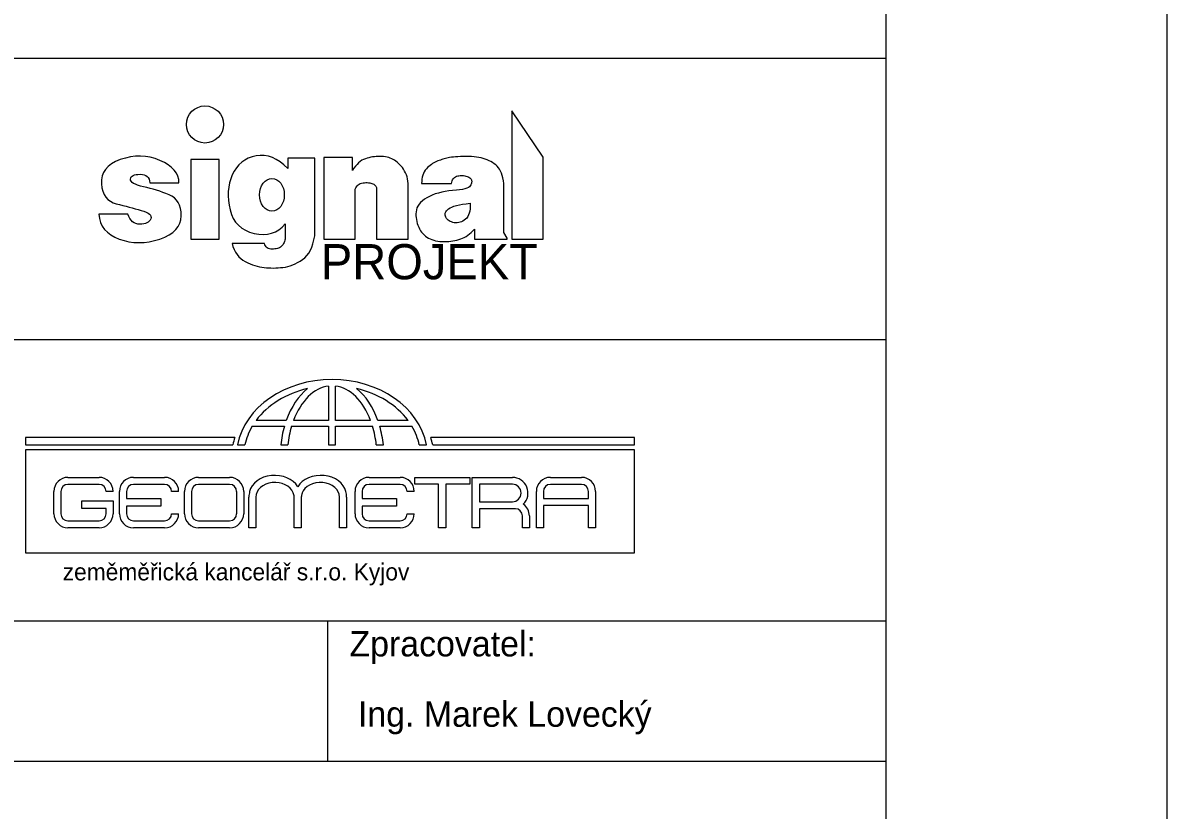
# Model space of a CAD drawing. Extents: x 1983 to 3683, y -706 to -261.
# Drawn here: x 2856.3 to 2937.6, y -606.5 to -550.5 of the extents above; entities that cross this region are included whole.
import ezdxf

# ---------------------------------------------------------------- set-up
doc = ezdxf.new("R2010")
doc.units = 0
for name, color, linetype in [('Default', 7, 'Continuous'), ('Komunikace', 7, 'Continuous'), ('Křížky', 7, 'Continuous'), ('Svazek obcí-chráničky', 7, 'Continuous'), ('Vrstva 51', 7, 'Continuous')]:
    doc.layers.add(name, color=color, linetype=linetype)

msp = doc.modelspace()

# ---------------------------------------------------------------- linework, layer by layer
at = {"layer": 'Default'}
msp.add_lwpolyline([(2727.602, -705.008), (2937.602, -705.008), (2937.602, -408.008), (2727.602, -408.008)], close=True, dxfattribs=at)
at = {"layer": 'Komunikace'}
for points in [[(2893.266, -565.887), (2893.266, -560.047), (2891.026, -556.767), (2891.026, -565.887), (2893.266, -565.887)], [(2864.538, -566.122), (2864.9, -566.105), (2865.266, -566.058), (2865.637, -565.979), (2866.013, -565.868), (2866.368, -565.732), (2866.676, -565.576), (2866.937, -565.4), (2867.151, -565.204), (2867.318, -564.988), (2867.439, -564.752), (2867.512, -564.496), (2867.539, -564.22), (2867.528, -563.947), (2867.49, -563.698), (2867.424, -563.474), (2867.33, -563.274), (2867.209, -563.1), (2867.059, -562.95), (2866.882, -562.824), (2866.678, -562.723), (2866.458, -562.637), (2866.236, -562.556), (2866.012, -562.478), (2865.786, -562.405), (2865.557, -562.337), (2865.326, -562.273), (2865.092, -562.213), (2864.857, -562.158), (2864.635, -562.103), (2864.444, -562.043), (2864.283, -561.98), (2864.153, -561.913), (2864.053, -561.842), (2863.983, -561.767), (2863.944, -561.688), (2863.936, -561.605), (2863.952, -561.525), (2863.989, -561.456), (2864.045, -561.398), (2864.121, -561.351), (2864.217, -561.315), (2864.332, -561.289), (2864.468, -561.275), (2864.623, -561.271), (2864.778, -561.282), (2864.914, -561.311), (2865.029, -561.358), (2865.123, -561.424), (2865.198, -561.508), (2865.253, -561.61), (2865.287, -561.73), (2865.302, -561.869), (2867.381, -561.869), (2867.361, -561.628), (2867.299, -561.398), (2867.194, -561.181), (2867.046, -560.976), (2866.856, -560.785), (2866.622, -560.606), (2866.345, -560.44), (2866.026, -560.287), (2865.684, -560.157), (2865.339, -560.063), (2864.991, -560.003), (2864.641, -559.978), (2864.288, -559.988), (2863.932, -560.033), (2863.574, -560.113), (2863.213, -560.227), (2862.875, -560.369), (2862.586, -560.532), (2862.345, -560.716), (2862.153, -560.919), (2862.009, -561.144), (2861.915, -561.389), (2861.868, -561.654), (2861.871, -561.94), (2861.91, -562.221), (2861.976, -562.473), (2862.069, -562.696), (2862.187, -562.889), (2862.332, -563.052), (2862.503, -563.186), (2862.7, -563.29), (2862.923, -563.365), (2863.158, -563.425), (2863.389, -563.484), (2863.617, -563.544), (2863.841, -563.603), (2864.061, -563.661), (2864.278, -563.72), (2864.491, -563.778), (2864.701, -563.835), (2864.893, -563.895), (2865.054, -563.96), (2865.185, -564.029), (2865.284, -564.102), (2865.353, -564.18), (2865.391, -564.262), (2865.398, -564.349), (2865.374, -564.441), (2865.327, -564.529), (2865.266, -564.605), (2865.191, -564.67), (2865.101, -564.723), (2864.997, -564.764), (2864.878, -564.794), (2864.745, -564.812), (2864.598, -564.819), (2864.45, -564.809), (2864.314, -564.776), (2864.19, -564.72), (2864.079, -564.641), (2863.98, -564.54), (2863.894, -564.416), (2863.82, -564.27), (2863.758, -564.102), (2861.678, -564.102), (2861.722, -564.408), (2861.805, -564.69), (2861.928, -564.948), (2862.091, -565.182), (2862.293, -565.391), (2862.535, -565.577), (2862.816, -565.737), (2863.137, -565.874), (2863.48, -565.983), (2863.828, -566.061), (2864.181, -566.107), (2864.538, -566.122)], [(2870.226, -565.887), (2870.226, -560.207), (2868.226, -560.207), (2868.226, -565.887), (2870.226, -565.887)], [(2874.086, -567.929), (2874.254, -567.926), (2874.424, -567.917), (2874.596, -567.904), (2874.77, -567.885), (2874.944, -567.858), (2875.118, -567.819), (2875.292, -567.768), (2875.465, -567.705), (2875.638, -567.629), (2875.811, -567.542), (2875.984, -567.442), (2876.156, -567.33), (2876.32, -567.2), (2876.469, -567.048), (2876.601, -566.872), (2876.718, -566.673), (2876.819, -566.451), (2876.904, -566.206), (2876.973, -565.938), (2877.026, -565.647), (2877.026, -560.127), (2875.106, -560.127), (2875.106, -560.847), (2874.84, -560.593), (2874.57, -560.379), (2874.295, -560.207), (2874.016, -560.076), (2873.733, -559.986), (2873.446, -559.938), (2873.154, -559.93), (2872.858, -559.963), (2872.571, -560.032), (2872.306, -560.128), (2872.062, -560.254), (2871.84, -560.408), (2871.64, -560.59), (2871.462, -560.801), (2871.306, -561.04), (2871.171, -561.308), (2871.06, -561.594), (2870.975, -561.887), (2870.916, -562.187), (2870.883, -562.495), (2870.876, -562.809), (2870.895, -563.131), (2870.94, -563.46), (2871.011, -563.796), (2871.111, -564.119), (2871.243, -564.41), (2871.409, -564.668), (2871.607, -564.893), (2871.838, -565.086), (2872.101, -565.246), (2872.397, -565.373), (2872.726, -565.468), (2873.062, -565.526), (2873.381, -565.544), (2873.681, -565.52), (2873.964, -565.456), (2874.229, -565.351), (2874.477, -565.206), (2874.707, -565.02), (2874.918, -564.793), (2874.918, -565.87), (2874.9, -565.957), (2874.877, -566.039), (2874.849, -566.115), (2874.817, -566.185), (2874.781, -566.249), (2874.74, -566.308), (2874.694, -566.361), (2874.644, -566.408), (2874.588, -566.45), (2874.526, -566.486), (2874.456, -566.517), (2874.379, -566.543), (2874.295, -566.563), (2874.204, -566.578), (2874.106, -566.587), (2874.001, -566.591), (2873.897, -566.586), (2873.804, -566.567), (2873.72, -566.535), (2873.647, -566.49), (2873.584, -566.432), (2873.532, -566.36), (2873.489, -566.275), (2873.457, -566.177), (2871.15, -566.177), (2871.219, -566.405), (2871.302, -566.614), (2871.399, -566.804), (2871.51, -566.975), (2871.635, -567.128), (2871.773, -567.262), (2871.926, -567.377), (2872.092, -567.474), (2872.264, -567.556), (2872.435, -567.63), (2872.604, -567.696), (2872.772, -567.753), (2872.938, -567.801), (2873.103, -567.841), (2873.266, -567.872), (2873.428, -567.895), (2873.59, -567.911), (2873.753, -567.922), (2873.919, -567.928), (2874.086, -567.929)], [(2883.666, -565.887), (2883.666, -562.087), (2883.663, -561.917), (2883.649, -561.754), (2883.624, -561.597), (2883.589, -561.447), (2883.543, -561.304), (2883.486, -561.167), (2883.418, -561.036), (2883.339, -560.913), (2883.254, -560.796), (2883.167, -560.688), (2883.078, -560.589), (2882.987, -560.497), (2882.894, -560.413), (2882.799, -560.338), (2882.702, -560.271), (2882.603, -560.212), (2882.501, -560.161), (2882.395, -560.117), (2882.284, -560.079), (2882.169, -560.049), (2882.049, -560.025), (2881.926, -560.009), (2881.798, -559.999), (2881.666, -559.996), (2881.532, -559.999), (2881.399, -560.008), (2881.268, -560.021), (2881.138, -560.039), (2881.009, -560.062), (2880.881, -560.089), (2880.754, -560.122), (2880.629, -560.16), (2880.505, -560.208), (2880.384, -560.273), (2880.265, -560.354), (2880.149, -560.452), (2880.034, -560.566), (2879.923, -560.696), (2879.813, -560.844), (2879.706, -561.007), (2879.706, -560.087), (2877.666, -560.087), (2877.666, -565.887), (2879.906, -565.887), (2879.906, -562.327), (2879.941, -562.236), (2879.985, -562.155), (2880.039, -562.084), (2880.104, -562.023), (2880.178, -561.972), (2880.262, -561.931), (2880.356, -561.9), (2880.46, -561.879), (2880.566, -561.866), (2880.666, -561.859), (2880.762, -561.858), (2880.852, -561.864), (2880.937, -561.875), (2881.017, -561.893), (2881.091, -561.916), (2881.16, -561.946), (2881.223, -561.981), (2881.277, -562.019), (2881.322, -562.061), (2881.36, -562.107), (2881.389, -562.156), (2881.41, -562.21), (2881.422, -562.266), (2881.426, -562.327), (2881.426, -565.887), (2883.666, -565.887)], [(2886.229, -566.051), (2886.391, -566.048), (2886.548, -566.04), (2886.702, -566.025), (2886.851, -566.005), (2886.995, -565.979), (2887.135, -565.948), (2887.271, -565.91), (2887.403, -565.867), (2887.532, -565.816), (2887.659, -565.755), (2887.784, -565.683), (2887.908, -565.6), (2888.03, -565.508), (2888.15, -565.404), (2888.269, -565.291), (2888.386, -565.167), (2888.386, -565.887), (2890.706, -565.887), (2890.706, -565.807), (2890.466, -565.407), (2890.466, -561.927), (2890.44, -561.722), (2890.404, -561.532), (2890.359, -561.357), (2890.304, -561.195), (2890.239, -561.049), (2890.165, -560.916), (2890.082, -560.798), (2889.989, -560.695), (2889.888, -560.602), (2889.78, -560.517), (2889.667, -560.438), (2889.547, -560.366), (2889.421, -560.301), (2889.288, -560.243), (2889.15, -560.192), (2889.005, -560.147), (2888.853, -560.11), (2888.694, -560.077), (2888.527, -560.051), (2888.354, -560.03), (2888.173, -560.015), (2887.985, -560.006), (2887.79, -560.002), (2887.588, -560.004), (2887.389, -560.01), (2887.205, -560.019), (2887.036, -560.029), (2886.881, -560.042), (2886.741, -560.057), (2886.616, -560.074), (2886.506, -560.093), (2886.41, -560.115), (2886.322, -560.139), (2886.232, -560.165), (2886.142, -560.192), (2886.051, -560.222), (2885.96, -560.253), (2885.868, -560.287), (2885.775, -560.322), (2885.682, -560.359), (2885.589, -560.401), (2885.496, -560.45), (2885.405, -560.505), (2885.315, -560.567), (2885.226, -560.636), (2885.138, -560.712), (2885.05, -560.795), (2884.964, -560.884), (2884.884, -560.982), (2884.815, -561.089), (2884.756, -561.205), (2884.709, -561.331), (2884.672, -561.466), (2884.646, -561.61), (2884.631, -561.764), (2884.626, -561.927), (2886.746, -561.927), (2886.762, -561.831), (2886.786, -561.743), (2886.819, -561.665), (2886.86, -561.597), (2886.91, -561.537), (2886.969, -561.486), (2887.036, -561.445), (2887.112, -561.413), (2887.193, -561.388), (2887.274, -561.37), (2887.355, -561.359), (2887.437, -561.354), (2887.52, -561.356), (2887.603, -561.364), (2887.687, -561.379), (2887.771, -561.4), (2887.851, -561.426), (2887.923, -561.454), (2887.985, -561.484), (2888.039, -561.516), (2888.084, -561.55), (2888.121, -561.586), (2888.148, -561.625), (2888.167, -561.665), (2888.178, -561.708), (2888.183, -561.754), (2888.182, -561.803), (2888.175, -561.854), (2888.161, -561.908), (2888.141, -561.965), (2888.115, -562.025), (2888.082, -562.087), (2888.032, -562.149), (2887.951, -562.205), (2887.839, -562.255), (2887.698, -562.301), (2887.526, -562.341), (2887.323, -562.375), (2887.091, -562.405), (2886.828, -562.429), (2886.556, -562.456), (2886.296, -562.493), (2886.049, -562.541), (2885.814, -562.599), (2885.591, -562.668), (2885.381, -562.748), (2885.183, -562.838), (2884.997, -562.939), (2884.828, -563.047), (2884.679, -563.159), (2884.552, -563.277), (2884.445, -563.398), (2884.36, -563.524), (2884.295, -563.655), (2884.251, -563.79), (2884.228, -563.93), (2884.22, -564.071), (2884.221, -564.212), (2884.231, -564.351), (2884.25, -564.489), (2884.278, -564.625), (2884.315, -564.761), (2884.361, -564.895), (2884.416, -565.028), (2884.479, -565.156), (2884.549, -565.276), (2884.626, -565.386), (2884.709, -565.487), (2884.8, -565.58), (2884.898, -565.664), (2885.002, -565.739), (2885.114, -565.805), (2885.232, -565.862), (2885.356, -565.913), (2885.486, -565.955), (2885.622, -565.989), (2885.765, -566.016), (2885.913, -566.036), (2886.068, -566.047), (2886.229, -566.051)], [(2886.945, -564.707), (2886.842, -564.686), (2886.747, -564.658), (2886.66, -564.622), (2886.581, -564.578), (2886.511, -564.527), (2886.448, -564.468), (2886.393, -564.401), (2886.346, -564.327), (2886.312, -564.249), (2886.294, -564.172), (2886.293, -564.096), (2886.308, -564.021), (2886.341, -563.947), (2886.39, -563.873), (2886.456, -563.801), (2886.538, -563.73), (2886.642, -563.661), (2886.77, -563.598), (2886.924, -563.541), (2887.103, -563.488), (2887.307, -563.441), (2887.537, -563.399), (2887.791, -563.363), (2888.071, -563.331), (2888.075, -563.53), (2888.067, -563.712), (2888.045, -563.878), (2888.01, -564.028), (2887.963, -564.161), (2887.902, -564.279), (2887.829, -564.38), (2887.743, -564.465), (2887.649, -564.536), (2887.554, -564.596), (2887.457, -564.644), (2887.358, -564.68), (2887.257, -564.704), (2887.155, -564.717), (2887.051, -564.717), (2886.945, -564.707)]]:
    msp.add_lwpolyline(points, dxfattribs=at)
msp.add_circle((2869.226, -557.727), 1.32, dxfattribs=at)
msp.add_ellipse((2873.986, -562.727), major_axis=(0, 1.16), ratio=0.758621, dxfattribs=at)
at = {"layer": 'Křížky'}
msp.add_lwpolyline([(2747.602, -428.008), (2917.602, -428.008), (2917.602, -688.008), (2747.602, -688.008)], close=True, dxfattribs=at)
at = {"layer": 'Svazek obcí-chráničky'}
for p, q in [((2877.997, -576.321), (2877.997, -578.766)), ((2878.504, -578.766), (2878.504, -576.318)), ((2875.003, -578.766), (2872.858, -578.766)), ((2877.997, -578.766), (2875.52, -578.766)), ((2880.998, -578.766), (2878.504, -578.766)), ((2883.66, -578.766), (2881.515, -578.766)), ((2872.583, -579.178), (2874.871, -579.178)), ((2875.381, -579.178), (2877.997, -579.178)), ((2877.997, -579.178), (2877.997, -580.498)), ((2878.504, -580.498), (2878.504, -579.178)), ((2878.504, -579.178), (2881.138, -579.178)), ((2881.648, -579.178), (2883.935, -579.178)), ((2871.352, -579.967), (2856.472, -579.967)), ((2856.472, -579.967), (2856.472, -580.498)), ((2856.472, -580.498), (2871.215, -580.498)), ((2871.54, -580.498), (2872.057, -580.498)), ((2874.614, -580.498), (2875.114, -580.498)), ((2877.997, -580.498), (2878.504, -580.498)), ((2881.405, -580.498), (2881.905, -580.498)), ((2884.461, -580.498), (2884.978, -580.498)), ((2899.75, -579.967), (2885.272, -579.967)), ((2885.41, -580.498), (2899.75, -580.498)), ((2899.75, -580.498), (2899.75, -579.967)), ((2899.749, -580.843), (2856.466, -580.843)), ((2856.466, -580.843), (2856.466, -588.181)), ((2899.749, -588.181), (2899.749, -580.843)), ((2859.491, -582.809), (2861.701, -582.809)), ((2864.147, -582.809), (2866.358, -582.809)), ((2868.771, -582.809), (2870.981, -582.809)), ((2880.889, -582.809), (2883.1, -582.809)), ((2888.227, -582.809), (2891.071, -582.809)), ((2893.775, -582.809), (2895.986, -582.809)), ((2858.493, -585.393), (2858.493, -583.806)), ((2858.992, -583.806), (2858.992, -585.393)), ((2861.701, -583.307), (2859.491, -583.307)), ((2862.699, -583.806), (2862.2, -583.806)), ((2863.149, -585.393), (2863.149, -583.806)), ((2863.648, -583.806), (2863.648, -584.317)), ((2866.358, -583.307), (2864.147, -583.307)), ((2867.355, -583.806), (2866.857, -583.806)), ((2867.773, -585.393), (2867.773, -583.806)), ((2868.272, -583.806), (2868.272, -585.393)), ((2870.981, -583.307), (2868.771, -583.307)), ((2871.481, -585.393), (2871.481, -583.806)), ((2871.979, -583.806), (2871.979, -585.393)), ((2879.892, -585.393), (2879.892, -583.806)), ((2880.39, -583.806), (2880.39, -584.317)), ((2883.1, -583.307), (2880.889, -583.307)), ((2884.098, -583.806), (2883.599, -583.806)), ((2885.832, -586.39), (2885.832, -583.295)), ((2886.336, -583.295), (2886.336, -586.39)), ((2891.071, -583.297), (2888.731, -583.297)), ((2888.731, -583.297), (2888.731, -584.547)), ((2892.777, -586.39), (2892.777, -583.806)), ((2893.276, -583.806), (2893.276, -584.315)), ((2895.986, -583.307), (2893.775, -583.307)), ((2896.485, -584.315), (2896.485, -583.806)), ((2896.983, -583.806), (2896.983, -586.39)), ((2860.466, -585.014), (2860.466, -584.47)), ((2860.466, -584.47), (2862.699, -584.47)), ((2862.699, -584.47), (2862.699, -585.393)), ((2863.648, -584.317), (2866.091, -584.317)), ((2866.091, -584.317), (2866.091, -584.862)), ((2872.352, -586.39), (2872.352, -584.205)), ((2872.852, -584.205), (2872.852, -586.39)), ((2875.572, -586.39), (2875.572, -584.205)), ((2876.072, -584.205), (2876.072, -586.39)), ((2878.791, -586.39), (2878.791, -584.205)), ((2879.291, -584.205), (2879.291, -586.39)), ((2880.39, -584.317), (2882.833, -584.317)), ((2882.833, -584.317), (2882.833, -584.862)), ((2888.731, -584.547), (2891.071, -584.547)), ((2893.276, -584.315), (2896.485, -584.315)), ((2862.2, -585.014), (2860.466, -585.014)), ((2862.2, -585.393), (2862.2, -585.014)), ((2866.091, -584.862), (2863.648, -584.862)), ((2863.648, -584.862), (2863.648, -585.393)), ((2866.857, -585.393), (2867.355, -585.393)), ((2882.833, -584.862), (2880.39, -584.862)), ((2880.39, -584.862), (2880.39, -585.393)), ((2883.599, -585.393), (2884.098, -585.393)), ((2891.071, -585.036), (2888.731, -585.036)), ((2891.285, -585.04), (2891.071, -585.036)), ((2896.485, -584.819), (2893.276, -584.819)), ((2893.276, -584.819), (2893.276, -586.39)), ((2896.485, -586.39), (2896.485, -584.819)), ((2859.491, -585.892), (2861.701, -585.892)), ((2864.147, -585.892), (2866.358, -585.892)), ((2868.771, -585.892), (2870.981, -585.892)), ((2880.889, -585.892), (2883.1, -585.892)), ((2891.784, -586.39), (2891.784, -585.539)), ((2892.283, -585.539), (2892.283, -586.39)), ((2861.701, -586.39), (2859.491, -586.39)), ((2866.358, -586.39), (2864.147, -586.39)), ((2870.981, -586.39), (2868.771, -586.39)), ((2872.852, -586.39), (2872.352, -586.39)), ((2876.072, -586.39), (2875.572, -586.39)), ((2879.291, -586.39), (2878.791, -586.39)), ((2883.1, -586.39), (2880.889, -586.39)), ((2886.336, -586.39), (2885.832, -586.39)), ((2892.283, -586.39), (2891.784, -586.39)), ((2893.276, -586.39), (2892.777, -586.39)), ((2896.983, -586.39), (2896.485, -586.39)), ((2856.466, -588.181), (2899.749, -588.181))]:
    msp.add_line(p, q, dxfattribs=at)
for points in [[(2885.832, -583.295), (2884.134, -583.295), (2884.134, -582.809), (2888.048, -582.809)], [(2888.048, -582.809), (2888.048, -583.295), (2886.336, -583.295)], [(2888.731, -585.036), (2888.731, -586.39), (2888.227, -586.39), (2888.227, -582.809)]]:
    msp.add_lwpolyline(points, dxfattribs=at)
for centre, radius, start, end in [((2859.491, -583.806), 0.998, 90, 180), ((2861.701, -583.806), 0.998, 360, 90), ((2864.147, -583.806), 0.998, 90, 180), ((2866.358, -583.806), 0.998, 360, 90), ((2868.771, -583.806), 0.998, 90, 180), ((2870.981, -583.806), 0.998, 360, 90), ((2880.889, -583.806), 0.998, 90, 180), ((2883.1, -583.806), 0.998, 360, 90), ((2891.071, -583.922), 1.114, 314.45734, 90), ((2893.775, -583.806), 0.998, 90, 180), ((2895.986, -583.806), 0.998, 360, 90), ((2859.491, -583.806), 0.499, 90, 180), ((2861.701, -583.806), 0.499, 0, 90), ((2864.147, -583.806), 0.499, 90, 180), ((2866.358, -583.806), 0.499, 0, 90), ((2868.771, -583.806), 0.499, 90, 180), ((2870.981, -583.806), 0.499, 0, 90), ((2874.289, -584.256), 1.938, 166.96576, 178.52091), ((2877.354, -584.256), 1.938, 1.47909, 13.03424), ((2880.889, -583.806), 0.499, 90, 180), ((2883.1, -583.806), 0.499, 0, 90), ((2891.071, -583.922), 0.625, 270, 90), ((2893.775, -583.806), 0.499, 90, 180), ((2895.986, -583.806), 0.499, 0, 90), ((2874.617, -584.27), 0.957, 3.86486, 22.41569), ((2877.305, -584.327), 1.238, 162.61388, 174.3506), ((2859.491, -585.393), 0.998, 180, 270), ((2859.491, -585.393), 0.499, 180, 270), ((2861.701, -585.393), 0.998, 270, 0), ((2861.701, -585.393), 0.499, 270, 0), ((2864.147, -585.393), 0.998, 180, 270), ((2864.147, -585.393), 0.499, 180, 270), ((2866.358, -585.393), 0.998, 270, 0), ((2866.358, -585.393), 0.499, 270, 0), ((2868.771, -585.393), 0.998, 180, 270), ((2868.771, -585.393), 0.499, 180, 270), ((2870.981, -585.393), 0.998, 270, 0), ((2870.981, -585.393), 0.499, 270, 0), ((2880.889, -585.393), 0.998, 180, 270), ((2880.889, -585.393), 0.499, 180, 270), ((2883.1, -585.393), 0.998, 270, 0), ((2883.1, -585.393), 0.499, 270, 0), ((2891.285, -585.539), 0.499, 0, 90), ((2891.285, -585.539), 0.998, 360, 55.44734)]:
    msp.add_arc(centre, radius, start, end, dxfattribs=at)
for centre, major_axis, ratio, start_param, end_param in [((2878.259, -581.371), (-6.804, 0), 0.811768, 3.300239, 6.124539), ((2878.259, -581.371), (-6.296, 0), 0.804826, 4.992897, 5.743383), ((2878.259, -581.371), (0, 5.524), 0.668443, 0.491666, 1.079789), ((2878.259, -581.371), (0, 5.067), 0.630136, 0.08224, 1.030995), ((2878.259, -581.371), (0, 5.067), 0.630136, 5.252191, 6.206521), ((2878.259, -581.371), (0, 5.524), 0.668443, 5.203397, 5.79152), ((2878.259, -581.371), (-6.296, 0), 0.804826, 3.681394, 4.431881), ((2878.259, -581.371), (-6.296, 0), 0.804826, 5.835664, 6.110118), ((2878.259, -581.371), (0, 5.524), 0.668443, 1.16256, 1.41215), ((2878.259, -581.371), (0, 5.067), 0.630136, 1.123275, 1.397729), ((2878.259, -581.371), (0, 5.067), 0.630136, 4.885456, 5.159911), ((2878.259, -581.371), (0, 5.524), 0.668443, 4.871035, 5.120625), ((2878.259, -581.371), (-6.296, 0), 0.804826, 3.31466, 3.589114), ((2877.933, -581.371), (-6.804, 0), 0.811768, 6.026233, 6.124539), ((2878.691, -581.371), (-6.804, 0), 0.811768, 3.300239, 3.398545), ((2874.181, -584.05), (1.805, 0), 0.766187, 0.429647, 2.97338), ((2877.462, -584.05), (-1.805, 0), 0.766187, 3.309805, 5.853538), ((2874.206, -584.205), (1.354, 0), 0.766187, 0.29376, 3.141593), ((2877.437, -584.205), (-1.354, 0), 0.766187, 3.141593, 6.041607)]:
    msp.add_ellipse(centre, major_axis=major_axis, ratio=ratio, start_param=start_param, end_param=end_param, dxfattribs=at)
at = {"layer": 'Vrstva 51'}
for p, q in [((2747.602, -573.008), (2917.602, -573.008)), ((2747.602, -593.008), (2917.602, -593.008)), ((2877.952, -603.008), (2877.952, -593.008))]:
    msp.add_line(p, q, dxfattribs=at)
msp.add_lwpolyline([(2747.602, -553.008), (2917.602, -553.008), (2917.602, -603.008), (2747.602, -603.008)], close=True, dxfattribs=at)

# ---------------------------------------------------------------- texts
at = {"layer": 'Komunikace'}
msp.add_text('PROJEKT', height=2.5, dxfattribs=at).set_placement((2877.467, -568.73))
at = {"layer": 'Svazek obcí-chráničky'}
msp.add_text('zeměměřická kancelář s.r.o. Kyjov', height=1.20984, dxfattribs=at).set_placement((2859.117, -590.13))
at = {"layer": 'Vrstva 51'}
for s, p in [('Zpracovatel:', (2879.498, -595.534)), ('Ing. Marek Lovecký', (2880.099, -600.534))]:
    msp.add_text(s, height=1.8, dxfattribs=at).set_placement(p)

doc.saveas('drawing.dxf')
